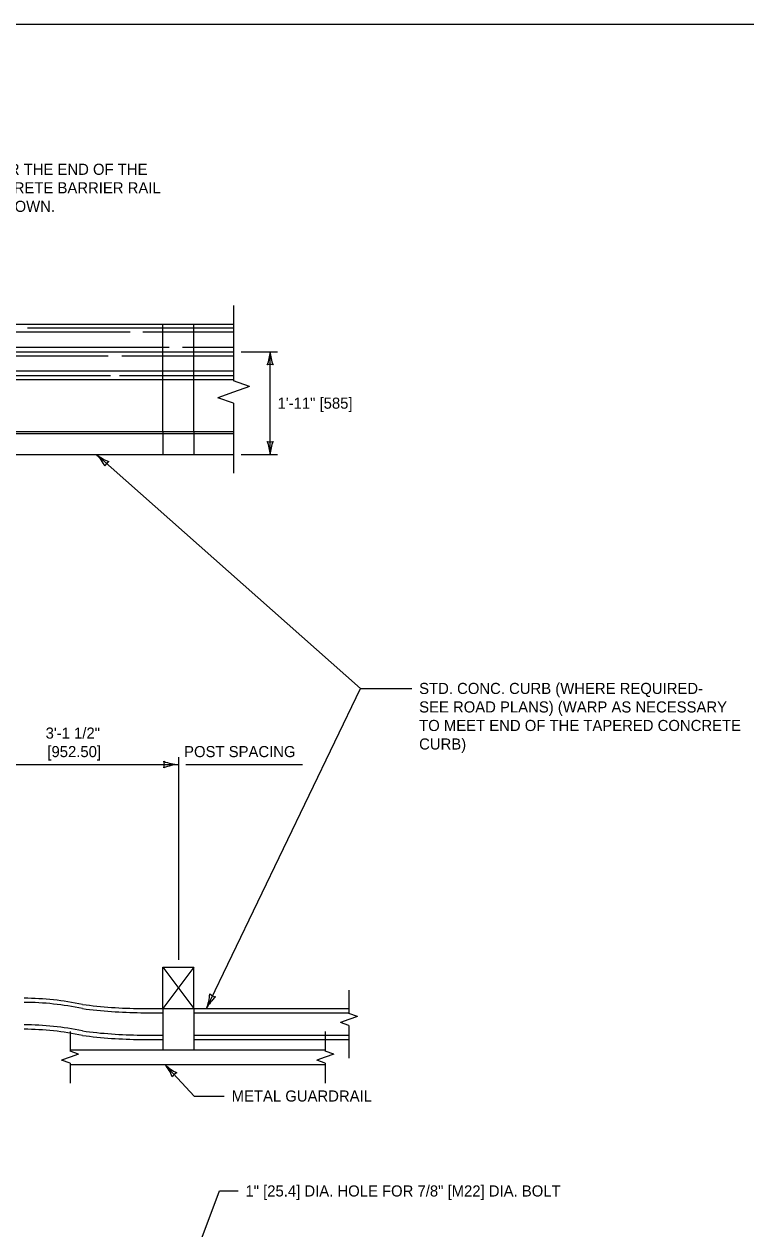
# Model space of a CAD drawing. Extents: x 49991.4 to 50021, y 49987.6 to 50011.4.
# Drawn here: x 50004.93 to 50008.83, y 49992.49 to 49999 of the extents above; entities that cross this region are included whole.
import ezdxf

# ---------------------------------------------------------------- set-up
doc = ezdxf.new("R2010")
doc.units = 0
for name, color, linetype in [('Level 1', 7, 'Continuous'), ('Level 2', 7, 'Continuous'), ('Level 3', 7, 'Continuous'), ('Level 4', 7, 'Continuous'), ('Level 6', 7, 'Continuous')]:
    doc.layers.add(name, color=color, linetype=linetype)

msp = doc.modelspace()

# ---------------------------------------------------------------- linework, layer by layer
at = {"layer": 'Level 1'}
for p, q in [((50002.0422, 49997.3798), (50006.0658, 49997.3798)), ((50004.9516, 49997.3599), (50006.0658, 49997.3599)), ((50004.082, 49997.3382), (50005.5076, 49997.3382)), ((50005.5754, 49997.3382), (50006.0658, 49997.3382)), ((50002.67, 49997.2301), (50006.0658, 49997.2301)), ((50004.7382, 49997.2548), (50005.7177, 49997.2548)), ((50005.7889, 49997.2548), (50006.0658, 49997.2548)), ((50004.2662, 49997.2083), (50005.388, 49997.2083)), ((50005.4623, 49997.2083), (50006.0658, 49997.2083)), ((50004.5798, 49997.1026), (50005.401, 49997.1026)), ((50004.7446, 49997.1274), (50006.0658, 49997.1274)), ((50005.4495, 49997.1026), (50006.0658, 49997.1026)), ((50002.0422, 49997.0804), (50006.0658, 49997.0804)), ((50005.6839, 49996.8004), (50005.6839, 49997.0804)), ((50005.8512, 49996.8004), (50005.8512, 49997.0804)), ((50004.8211, 49996.8004), (50006.0658, 49996.8004)), ((50004.8211, 49996.7886), (50006.0658, 49996.7886)), ((50001.2358, 49996.6755), (50006.0658, 49996.6755)), ((50005.6839, 49993.9076), (50005.8512, 49993.9076)), ((50005.6839, 49993.6845), (50005.6839, 49993.9076)), ((50005.8512, 49993.9076), (50005.6839, 49993.6845)), ((50005.6839, 49993.9076), (50005.8512, 49993.6845)), ((50005.8512, 49993.6845), (50005.8512, 49993.9076)), ((50005.5639, 49993.6845), (50005.6839, 49993.6845)), ((50005.5639, 49993.6623), (50005.6839, 49993.6623)), ((50005.6839, 49993.6845), (50005.6839, 49993.4614)), ((50005.6839, 49993.6845), (50005.8512, 49993.6845)), ((50005.8512, 49993.6845), (50005.8512, 49993.4614)), ((50005.8512, 49993.6845), (50006.6886, 49993.6845)), ((50005.8512, 49993.6623), (50006.6886, 49993.6623)), ((50005.5639, 49993.5412), (50005.6839, 49993.5412)), ((50005.5639, 49993.5172), (50005.6839, 49993.5172)), ((50005.8512, 49993.5412), (50006.6886, 49993.5412)), ((50005.8512, 49993.5171), (50006.6886, 49993.5171)), ((50005.1822, 49993.4614), (50005.8752, 49993.4614)), ((50005.8674, 49993.4614), (50006.5605, 49993.4614)), ((50005.1822, 49993.3824), (50005.8713, 49993.3824)), ((50005.8713, 49993.3824), (50006.5605, 49993.3824))]:
    msp.add_line(p, q, dxfattribs=at)
msp.add_lwpolyline([(49999.3835, 49998.9992), (50016.7501, 49998.9992), (50016.7501, 49987.7988), (49999.3835, 49987.7988)], close=True, dxfattribs=at)
for centre, radius, start, end in [((50004.9245, 49992.1539), 1.5864, 78.19946, 89.65864), ((50004.9245, 49992.1316), 1.5864, 78.19946, 89.65864), ((50005.5961, 49996.3768), 2.6925, 262.59152, 269.31498), ((50005.5961, 49996.3546), 2.6925, 262.59152, 269.31498), ((50004.9245, 49992.0106), 1.5864, 78.19946, 89.65864), ((50004.9245, 49991.9866), 1.5864, 78.19946, 89.65864), ((50005.5961, 49996.2335), 2.6925, 262.59152, 269.31498), ((50005.5961, 49996.2095), 2.6925, 262.59152, 269.31498)]:
    msp.add_arc(centre, radius, start, end, dxfattribs=at)
at = {"layer": 'Level 3'}
for p, q in [((50006.1058, 49997.2301), (50006.303, 49997.2301)), ((50006.263, 49996.6755), (50006.263, 49997.2301)), ((50006.751, 49995.4128), (50005.3244, 49996.6755)), ((50006.1058, 49996.6755), (50006.303, 49996.6755)), ((50005.9184, 49993.6845), (50006.751, 49995.4128)), ((50006.7511, 49995.4128), (50007.0277, 49995.4128)), ((50005.7683, 49995.0417), (50005.7683, 49993.9476)), ((50004.7225, 49995.0017), (50005.7683, 49995.0017)), ((50005.8083, 49995.0017), (50006.4379, 49995.0017)), ((50005.695, 49993.3824), (50005.8535, 49993.2124)), ((50005.8535, 49993.2124), (50006.0151, 49993.2124)), ((50005.81, 49992.2243), (50005.9895, 49992.6998)), ((50005.9895, 49992.6998), (50006.0896, 49992.6998))]:
    msp.add_line(p, q, dxfattribs=at)
for centre, radius, start, end in [((50006.0561, 49997.2386), 0.2071, 337.45601, 357.63952), ((50006.4798, 49997.2408), 0.2171, 182.82731, 202.07716), ((50006.263, 49997.1107), 0.051, 72.13882, 107.86118), ((50006.263, 49996.7949), 0.051, 252.13882, 287.86118), ((50006.0462, 49996.6648), 0.2171, 2.82731, 22.07716), ((50006.4699, 49996.667), 0.2071, 157.45601, 177.63952), ((50005.1703, 49996.5152), 0.2223, 25.94389, 46.12739), ((50005.47, 49996.8574), 0.233, 231.31519, 250.56504), ((50005.4204, 49996.5905), 0.0548, 120.62669, 156.34906), ((50005.7779, 49995.234), 0.2325, 247.45601, 267.63952), ((50005.6342, 49995.0017), 0.0573, 342.13882, 17.86118), ((50005.7803, 49994.7584), 0.2437, 92.82731, 112.07716), ((50005.6939, 49993.7793), 0.2437, 337.1024, 356.35225), ((50006.1235, 49993.575), 0.2325, 131.7311, 151.91461), ((50005.9766, 49993.8053), 0.0573, 226.41391, 262.13627), ((50005.5262, 49993.2377), 0.2223, 20.42931, 40.61281), ((50005.8574, 49993.5494), 0.233, 225.80061, 245.05046), ((50005.7824, 49993.2886), 0.0548, 115.11211, 150.83447)]:
    msp.add_arc(centre, radius, start, end, dxfattribs=at)
at = {"layer": 'Level 4'}
for p, q in [((50005.6839, 49997.0804), (50005.6839, 49997.3798)), ((50005.8512, 49997.0804), (50005.8512, 49997.3798)), ((50005.6839, 49996.8004), (50005.6839, 49996.6755)), ((50005.8512, 49996.8004), (50005.8512, 49996.6755))]:
    msp.add_line(p, q, dxfattribs=at)
at = {"layer": 'Level 6'}
for p, q in [((50006.0658, 49997.4798), (50006.0658, 49997.0729)), ((50006.151, 49997.0427), (50006.0658, 49997.0729)), ((50006.151, 49997.0427), (50006.0658, 49997.0125)), ((50006.0658, 49997.0125), (50005.9807, 49996.9823)), ((50006.0658, 49996.9521), (50005.9807, 49996.9823)), ((50006.0658, 49996.9521), (50006.0658, 49996.5755)), ((50006.6886, 49993.7845), (50006.6886, 49993.6577)), ((50006.7343, 49993.6415), (50006.6886, 49993.6577)), ((50006.7343, 49993.6415), (50006.6886, 49993.6253)), ((50006.6886, 49993.6253), (50006.6429, 49993.6091)), ((50006.6886, 49993.5929), (50006.6429, 49993.6091)), ((50006.6886, 49993.5929), (50006.6886, 49993.4171)), ((50005.1822, 49993.5614), (50005.1822, 49993.4543)), ((50006.5605, 49993.5614), (50006.5605, 49993.4543)), ((50005.2279, 49993.4381), (50005.1822, 49993.4543)), ((50006.6062, 49993.4381), (50006.5605, 49993.4543)), ((50005.1822, 49993.4219), (50005.1365, 49993.4057)), ((50005.1822, 49993.3895), (50005.1365, 49993.4057)), ((50005.2279, 49993.4381), (50005.1822, 49993.4219)), ((50005.1822, 49993.3895), (50005.1822, 49993.2824)), ((50006.5605, 49993.4219), (50006.5148, 49993.4057)), ((50006.5605, 49993.3895), (50006.5148, 49993.4057)), ((50006.6062, 49993.4381), (50006.5605, 49993.4219)), ((50006.5605, 49993.3895), (50006.5605, 49993.2824))]:
    msp.add_line(p, q, dxfattribs=at)

# ---------------------------------------------------------------- texts
at = {"layer": 'Level 2'}
for s, p in [('TAPER THE END OF THE', (50004.642, 49998.1854)), ('CONCRETE BARRIER RAIL', (50004.642, 49998.0854)), ('AS SHOWN.', (50004.642, 49997.9854)), ('1\'-11" [585]', (50006.303, 49996.9228)), ('STD. CONC. CURB (WHERE REQUIRED-', (50007.0677, 49995.3828)), ('SEE ROAD PLANS) (WARP AS NECESSARY', (50007.0677, 49995.2828)), ('3\'-1 1/2"', (50005.0503, 49995.1417)), ('TO MEET END OF THE TAPERED CONCRETE ', (50007.0677, 49995.1828)), ('CURB)', (50007.0677, 49995.0828)), ('[952.50]', (50005.0596, 49995.0417)), ('POST SPACING', (50005.7983, 49995.0417)), ('METAL GUARDRAIL', (50006.0551, 49993.1824)), ('1" [25.4] DIA. HOLE FOR 7/8" [M22] DIA. BOLT', (50006.1296, 49992.6698))]:
    msp.add_text(s, height=0.06, dxfattribs=at).set_placement(p)

doc.saveas('drawing.dxf')
